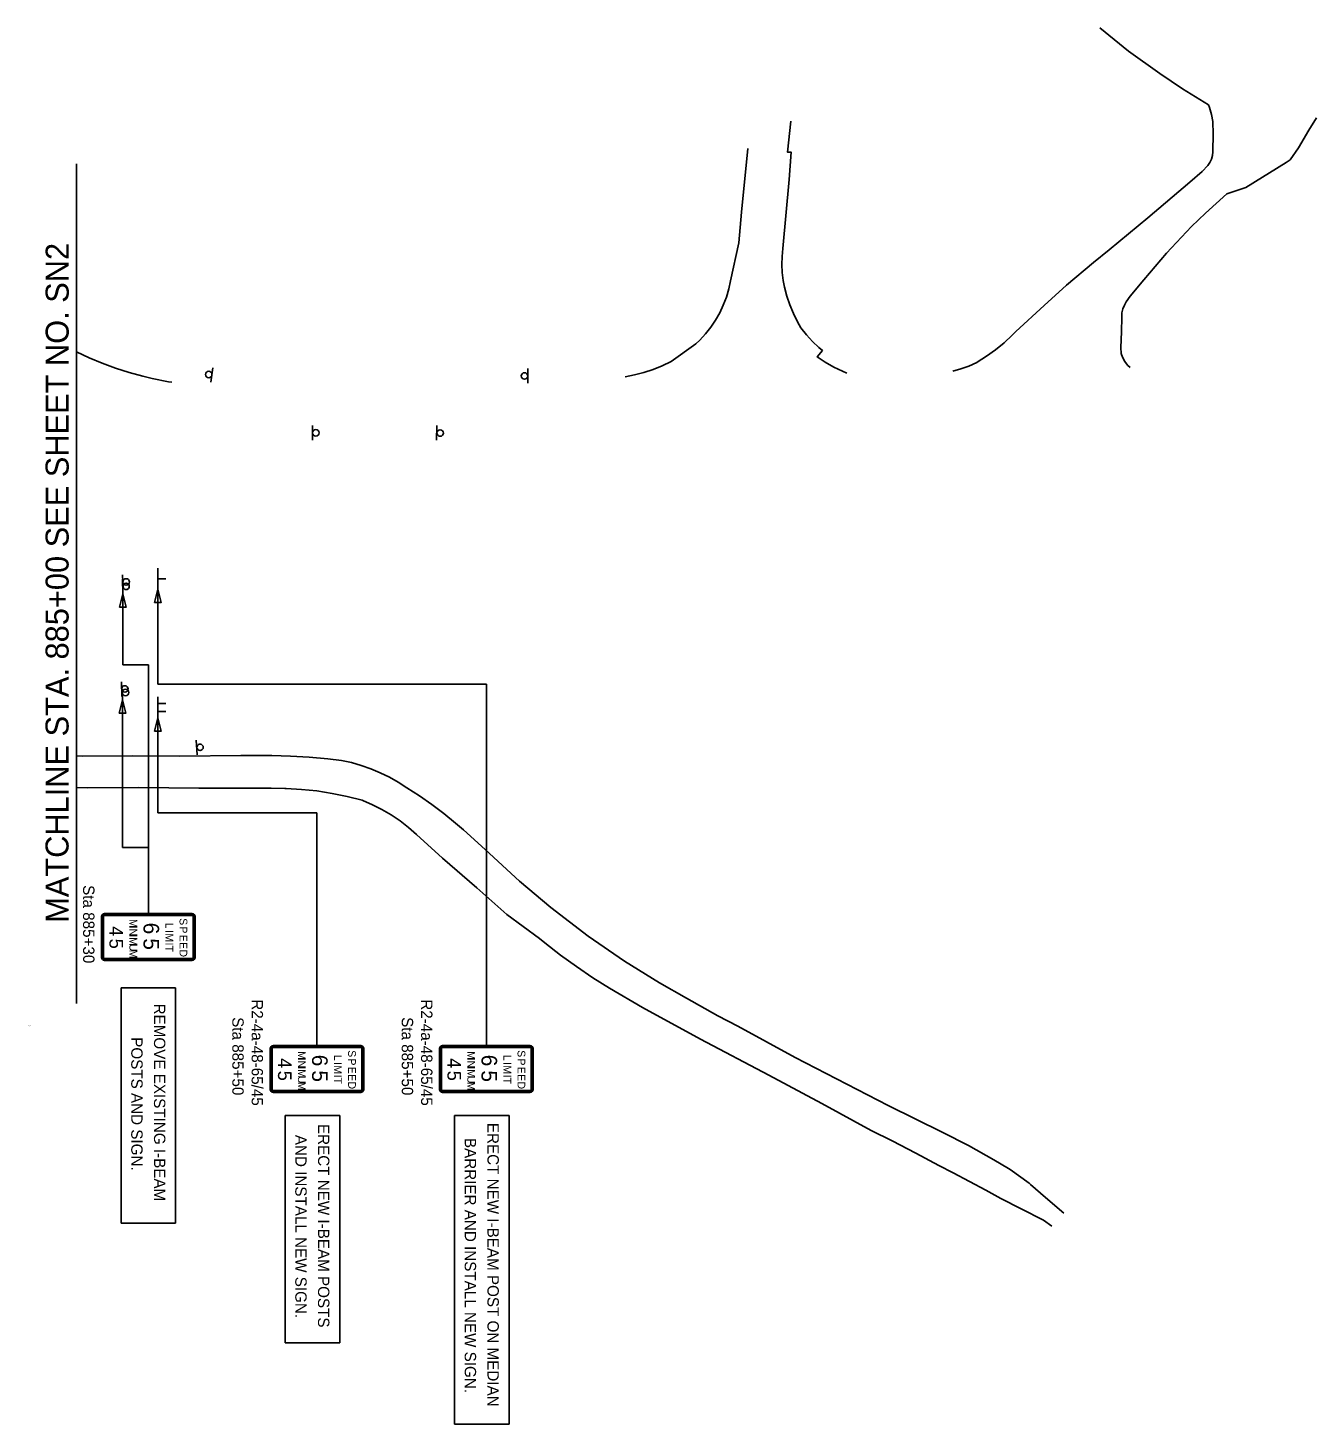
# Model space of a CAD drawing. Extents: x 1738774 to 1740360, y 1165523 to 1166492.
# Drawn here: x 1738774 to 1739567, y 1165523 to 1166383 of the extents above; entities that cross this region are included whole.
import ezdxf

# ---------------------------------------------------------------- set-up
doc = ezdxf.new("R2010")
doc.units = 0
for name, color, linetype in [('Default', 7, 'Continuous'), ('RD_EX_Road', 7, 'Continuous'), ('RD_SHT_MatchLine', 7, 'Continuous'), ('RD_SHT_TX', 7, 'Continuous'), ('SN_P_Signs', 7, 'Continuous')]:
    doc.layers.add(name, color=color, linetype=linetype)

msp = doc.modelspace()

# ---------------------------------------------------------------- linework, layer by layer
at = {"layer": 'RD_EX_Road'}
for points in [[(1739343.56, 1166171.83), (1739348.43, 1166173.2), (1739353.41, 1166175), (1739358.24, 1166177.18), (1739358.48, 1166177.3), (1739364.22, 1166180.98), (1739369.74, 1166184.98), (1739375.01, 1166189.3), (1739380.03, 1166193.91), (1739382.33, 1166196.21), (1739399.67, 1166212.18), (1739413.57, 1166224.69), (1739430.1, 1166238.68), (1739439.71, 1166246.44), (1739463.52, 1166266.19), (1739489.38, 1166288.25), (1739497.13, 1166294.74), (1739500.52, 1166298.46), (1739501.82, 1166300.32), (1739502.78, 1166302.38), (1739503.38, 1166304.57), (1739503.58, 1166306.84), (1739503.57, 1166307.3), (1739503.93, 1166317.85), (1739503.66, 1166325.46), (1739502.8, 1166329.83), (1739501.55, 1166334.1), (1739500.95, 1166335.76), (1739484.91, 1166345.58), (1739470.92, 1166355.04), (1739451.7, 1166368.78), (1739433.95, 1166383.18)], [(1739243.77, 1166325.81), (1739241.61, 1166306.77), (1739243.94, 1166306.58), (1739242.62, 1166289.86), (1739238.8, 1166247.42), (1739238.26, 1166242.48), (1739238.11, 1166237.51), (1739238.36, 1166232.55), (1739239, 1166227.62), (1739239.83, 1166223.56), (1739241.27, 1166218.02), (1739243.09, 1166212.6), (1739245.27, 1166207.31), (1739247.82, 1166202.19), (1739249.94, 1166198.49), (1739253.29, 1166194.2), (1739256.94, 1166190.16), (1739260.87, 1166186.4), (1739263.14, 1166184.46), (1739259.97, 1166180.57), (1739264.93, 1166177.3), (1739270.09, 1166174.36), (1739275.44, 1166171.77), (1739278.26, 1166170.63)], [(1739567.51, 1166327.79), (1739562.69, 1166320.3), (1739556.33, 1166309.34), (1739551.25, 1166302.04), (1739548.74, 1166300.37), (1739524.01, 1166284.98), (1739512.22, 1166281.11), (1739499.03, 1166269.04), (1739490.5, 1166260.93), (1739475.09, 1166244.45), (1739461.07, 1166227.99), (1739452.7, 1166217.92), (1739450.25, 1166214.49), (1739449.15, 1166212.56), (1739448.22, 1166210.17), (1739447.66, 1166207.67), (1739447.49, 1166205.12), (1739447.45, 1166196.13), (1739447.02, 1166186.49), (1739447.16, 1166182.73), (1739448.03, 1166180.45), (1739449.41, 1166177.86), (1739451.13, 1166175.48), (1739452.71, 1166174.02)], [(1739217.17, 1166308.92), (1739213.22, 1166269.83), (1739211.69, 1166250.8), (1739206.59, 1166227.55), (1739205.47, 1166222.44), (1739203.97, 1166217.43), (1739202.1, 1166212.55), (1739199.86, 1166207.83), (1739197.28, 1166203.29), (1739194.36, 1166198.95), (1739191.12, 1166194.85), (1739187.58, 1166191), (1739185.21, 1166188.73), (1739169.92, 1166177.74), (1739164.49, 1166175.13), (1739158.91, 1166172.88), (1739153.2, 1166171), (1739147.37, 1166169.5), (1739141.56, 1166168.41)], [(1738862.33, 1166165.02), (1738860.41, 1166165.33), (1738850.21, 1166167.38), (1738844.5, 1166168.7), (1738836.05, 1166170.99), (1738827.72, 1166173.66), (1738819.51, 1166176.71), (1738811.45, 1166180.12), (1738803.73, 1166183.8)], [(1738803.73, 1165934.87), (1738807.57, 1165934.84), (1738838.18, 1165934.92), (1738867.23, 1165934.84), (1738904.83, 1165935.06), (1738923.98, 1165935.14), (1738935.5, 1165934.85), (1738947.01, 1165934.17), (1738958.48, 1165933.09), (1738966.84, 1165932.06), (1738972.99, 1165930.76), (1738979.04, 1165929.07), (1738984.98, 1165927.01), (1738990.78, 1165924.58), (1738996.41, 1165921.78), (1739001.86, 1165918.65), (1739007.06, 1165915.2), (1739014.94, 1165910.27), (1739022.6, 1165905.01), (1739030.04, 1165899.43), (1739037.22, 1165893.54), (1739041.96, 1165889.37), (1739055.31, 1165877.27), (1739076.59, 1165857.76), (1739095.93, 1165841.52), (1739118.82, 1165823.93), (1739141.13, 1165808.47), (1739162.69, 1165795.26), (1739179.48, 1165785.83), (1739198.66, 1165774.79), (1739211, 1165768.54), (1739246.43, 1165749.26), (1739303.66, 1165719.64), (1739337.22, 1165702.99), (1739353.19, 1165694.92), (1739368.83, 1165686.17), (1739377.83, 1165680.77), (1739378.7, 1165680.25), (1739390.47, 1165671.75), (1739391.32, 1165671), (1739400.52, 1165662.94), (1739411.96, 1165653.33)], [(1738803.73, 1165915.38), (1738810.52, 1165915.34), (1738842.13, 1165915.46), (1738879.01, 1165915.07), (1738907.68, 1165915.04), (1738923.61, 1165914.97), (1738932.03, 1165914.83), (1738932.91, 1165914.75), (1738942.34, 1165914.23), (1738951.74, 1165913.31), (1738961.09, 1165911.81), (1738970.37, 1165909.92), (1738979.57, 1165907.65), (1738979.95, 1165907.5), (1738985.97, 1165904.87), (1738991.83, 1165901.88), (1738997.49, 1165898.55), (1739002.94, 1165894.89), (1739008.17, 1165890.9), (1739013.14, 1165886.61), (1739029.14, 1165871.95), (1739050.29, 1165853.65), (1739068.74, 1165837.19), (1739088.89, 1165822.5), (1739092.25, 1165819.77), (1739101.83, 1165812.31), (1739111.64, 1165805.17), (1739121.68, 1165798.35), (1739131.94, 1165791.86), (1739152.32, 1165779.92), (1739188.09, 1165760.47), (1739230.24, 1165738.34), (1739262.78, 1165720.95), (1739293.27, 1165704.27), (1739306.16, 1165697.89), (1739320.76, 1165690.38), (1739334.77, 1165682.75), (1739343.64, 1165678.09), (1739353.77, 1165672.79), (1739363.83, 1165667.51), (1739373.07, 1165662.47), (1739385.59, 1165655.93), (1739399.34, 1165649.13), (1739404.54, 1165645.36)]]:
    msp.add_lwpolyline(points, dxfattribs=at)
at = {"layer": 'RD_SHT_MatchLine'}
msp.add_lwpolyline([(1738803.73, 1165782.42), (1738803.73, 1166044.04), (1738803.73, 1166299.49)], dxfattribs=at)
at = {"layer": 'SN_P_Signs'}
for p, q in [((1738886.5, 1166164.99), (1738887.68, 1166173.91)), ((1739081.75, 1166164.38), (1739081.61, 1166173.38)), ((1738948.98, 1166138.34), (1738949.11, 1166129.34)), ((1739025.73, 1166138.3), (1739025.5, 1166129.3)), ((1738853.73, 1166037.52), (1738853.73, 1166050.56)), ((1738832.03, 1166043.77), (1738832.29, 1166034.77)), ((1738832.09, 1166046.49), (1738832.35, 1166037.5)), ((1738853.73, 1165979), (1738853.73, 1166044.04)), ((1738853.73, 1166044.04), (1738858.72, 1166044.04)), ((1738832.29, 1165991.08), (1738832.29, 1166034.77)), ((1738832.29, 1165991.08), (1738847.94, 1165991.08)), ((1738847.94, 1165837.82), (1738847.94, 1165991.08)), ((1738831.34, 1165980.59), (1738831.6, 1165971.59)), ((1738831.66, 1165978.39), (1738831.92, 1165969.4)), ((1738853.73, 1165979), (1739056.14, 1165979)), ((1739056.14, 1165756.51), (1739056.14, 1165979)), ((1738853.73, 1165958.27), (1738853.73, 1165971.31)), ((1738831.92, 1165878.58), (1738831.92, 1165969.4)), ((1738853.73, 1165967.2), (1738858.72, 1165967.2)), ((1738853.73, 1165962.18), (1738858.72, 1165962.18)), ((1738853.73, 1165899.82), (1738853.73, 1165958.27)), ((1738877.46, 1165944.58), (1738878.01, 1165935.6)), ((1738853.73, 1165899.82), (1738951.77, 1165899.82)), ((1738951.77, 1165756.51), (1738951.77, 1165899.82)), ((1738831.92, 1165878.58), (1738847.94, 1165878.58)), ((1738819.14, 1165810.82), (1738819.14, 1165836.02)), ((1738820.94, 1165837.82), (1738874.94, 1165837.82)), ((1738876.74, 1165836.02), (1738876.74, 1165810.82)), ((1738874.94, 1165809.02), (1738820.94, 1165809.02)), ((1738831.13, 1165647.11), (1738831.13, 1165792.13)), ((1738831.13, 1165792.13), (1738864.75, 1165792.13)), ((1738864.75, 1165792.13), (1738864.75, 1165647.11)), ((1738922.97, 1165729.51), (1738922.97, 1165754.71)), ((1738924.77, 1165756.51), (1738978.77, 1165756.51)), ((1738980.57, 1165754.71), (1738980.57, 1165729.51)), ((1739027.34, 1165729.51), (1739027.34, 1165754.71)), ((1739029.14, 1165756.51), (1739083.14, 1165756.51)), ((1739084.94, 1165754.71), (1739084.94, 1165729.51)), ((1738978.77, 1165727.71), (1738924.77, 1165727.71)), ((1739083.14, 1165727.71), (1739029.14, 1165727.71)), ((1738932.17, 1165573.46), (1738932.17, 1165713.48)), ((1738932.17, 1165713.48), (1738965.79, 1165713.48)), ((1738965.79, 1165713.48), (1738965.79, 1165573.46)), ((1739036.54, 1165523.46), (1739036.54, 1165713.48)), ((1739036.54, 1165713.48), (1739070.16, 1165713.48)), ((1739070.16, 1165713.48), (1739070.16, 1165523.46)), ((1738864.75, 1165647.11), (1738831.13, 1165647.11)), ((1738965.79, 1165573.46), (1738932.17, 1165573.46)), ((1739070.16, 1165523.46), (1739036.54, 1165523.46))]:
    msp.add_line(p, q, dxfattribs=at)
for points in [[(1738830.24, 1166026.57), (1738832.29, 1166034.77), (1738834.34, 1166026.57)], [(1738851.68, 1166029.32), (1738853.73, 1166037.52), (1738855.79, 1166029.32)], [(1738829.86, 1165961.19), (1738831.92, 1165969.4), (1738833.97, 1165961.19)], [(1738851.68, 1165950.07), (1738853.73, 1165958.27), (1738855.79, 1165950.07)]]:
    msp.add_lwpolyline(points, close=True, dxfattribs=at)
for points in [[(1738819.59, 1165810.82), (1738819.59, 1165836.02)], [(1738820.34, 1165810.82), (1738820.34, 1165836.02)], [(1738820.94, 1165837.37), (1738874.94, 1165837.37)], [(1738820.94, 1165836.62), (1738874.94, 1165836.62)], [(1738875.54, 1165836.02), (1738875.54, 1165810.82)], [(1738876.29, 1165836.02), (1738876.29, 1165810.82)], [(1738874.94, 1165810.22), (1738820.94, 1165810.22)], [(1738874.94, 1165809.47), (1738820.94, 1165809.47)], [(1738923.42, 1165729.51), (1738923.42, 1165754.71)], [(1738924.17, 1165729.51), (1738924.17, 1165754.71)], [(1738924.77, 1165756.06), (1738978.77, 1165756.06)], [(1738924.77, 1165755.31), (1738978.77, 1165755.31)], [(1738979.37, 1165754.71), (1738979.37, 1165729.51)], [(1738980.12, 1165754.71), (1738980.12, 1165729.51)], [(1739027.79, 1165729.51), (1739027.79, 1165754.71)], [(1739028.54, 1165729.51), (1739028.54, 1165754.71)], [(1739029.14, 1165756.06), (1739083.14, 1165756.06)], [(1739029.14, 1165755.31), (1739083.14, 1165755.31)], [(1739083.74, 1165754.71), (1739083.74, 1165729.51)], [(1739084.49, 1165754.71), (1739084.49, 1165729.51)], [(1738978.77, 1165728.91), (1738924.77, 1165728.91)], [(1738978.77, 1165728.16), (1738924.77, 1165728.16)], [(1739083.14, 1165728.91), (1739029.14, 1165728.91)], [(1739083.14, 1165728.16), (1739029.14, 1165728.16)]]:
    msp.add_lwpolyline(points, dxfattribs=at)
for centre in [(1738885.09, 1166169.73), (1739079.65, 1166168.86), (1738951.07, 1166133.85), (1739027.64, 1166133.73), (1738834.19, 1166039.31), (1738834.24, 1166042.03), (1738833.49, 1165976.13), (1738833.81, 1165973.93), (1738879.76, 1165940.2)]:
    msp.add_circle(centre, 2, dxfattribs=at)
for centre, radius, start, end in [((1738820.94, 1165836.02), 1.8, 90, 180), ((1738820.94, 1165836.02), 1.35, 90, 180), ((1738820.94, 1165836.02), 0.6, 90, 180), ((1738874.94, 1165836.02), 1.8, 0, 90), ((1738874.94, 1165836.02), 1.35, 0, 90), ((1738874.94, 1165836.02), 0.6, 0, 90), ((1738820.94, 1165810.82), 1.8, 180, 270), ((1738820.94, 1165810.82), 1.35, 180, 270), ((1738820.94, 1165810.82), 0.6, 180, 270), ((1738874.94, 1165810.82), 0.6, 270, 0), ((1738874.94, 1165810.82), 1.35, 270, 0), ((1738874.94, 1165810.82), 1.8, 270, 0), ((1738924.77, 1165754.71), 1.8, 90, 180), ((1738924.77, 1165754.71), 1.35, 90, 180), ((1738924.77, 1165754.71), 0.6, 90, 180), ((1738978.77, 1165754.71), 1.8, 0, 90), ((1738978.77, 1165754.71), 1.35, 0, 90), ((1738978.77, 1165754.71), 0.6, 0, 90), ((1739029.14, 1165754.71), 1.8, 90, 180), ((1739029.14, 1165754.71), 1.35, 90, 180), ((1739029.14, 1165754.71), 0.6, 90, 180), ((1739083.14, 1165754.71), 1.8, 0, 90), ((1739083.14, 1165754.71), 1.35, 0, 90), ((1739083.14, 1165754.71), 0.6, 0, 90), ((1738924.77, 1165729.51), 1.8, 180, 270), ((1738924.77, 1165729.51), 1.35, 180, 270), ((1738924.77, 1165729.51), 0.6, 180, 270), ((1738978.77, 1165729.51), 0.6, 270, 0), ((1738978.77, 1165729.51), 1.35, 270, 0), ((1738978.77, 1165729.51), 1.8, 270, 0), ((1739029.14, 1165729.51), 1.8, 180, 270), ((1739029.14, 1165729.51), 1.35, 180, 270), ((1739029.14, 1165729.51), 0.6, 180, 270), ((1739083.14, 1165729.51), 0.6, 270, 0), ((1739083.14, 1165729.51), 1.35, 270, 0), ((1739083.14, 1165729.51), 1.8, 270, 0)]:
    msp.add_arc(centre, radius, start, end, dxfattribs=at)

# ---------------------------------------------------------------- texts
at = {"layer": 'Default'}
for s, height, p in [('Angle:  16.0848', 0.2083, (1738773.73, 1165768.56)), ('Align: A_I85', 0.2083, (1738773.73, 1165768.29)), ('Sheet: 3', 0.208, (1738773.73, 1165768.83))]:
    msp.add_text(s, height=height, dxfattribs=at).set_placement(p)
at = {"layer": 'RD_SHT_TX'}
msp.add_text('MATCHLINE STA. 885+00 SEE SHEET NO. SN2', height=14.1726, rotation=89.98556, dxfattribs=at).set_placement((1738798.75, 1165832.14))
at = {"layer": 'SN_P_Signs'}
for s, height, rotation, p in [('Sta 885+30', 7, 270.00008, (1738807.72, 1165855.33)), ('M', 4.8, 270, (1738836.24, 1165834.42)), ('S', 4.8, 270, (1738867.14, 1165834.97)), ('4', 8.4, 270, (1738823.94, 1165830.11)), ('I', 4.8, 270, (1738836.24, 1165830.3)), ('N', 4.8, 270, (1738836.24, 1165828.61)), ('I', 4.8, 270, (1738836.24, 1165824.97)), ('6', 9.6, 270, (1738844.94, 1165832.21)), ('L', 4.8, 270, (1738858.44, 1165832.21)), ('I', 4.8, 270, (1738858.44, 1165827.69)), ('M', 4.8, 270, (1738858.44, 1165825.63)), ('P', 4.8, 270, (1738867.14, 1165829.87)), ('E', 4.8, 270, (1738867.14, 1165824.78)), ('5', 8.4, 270, (1738823.94, 1165822.37)), ('U', 4.8, 270, (1738836.24, 1165819.17)), ('M', 4.8, 270, (1738836.24, 1165823.29)), ('M', 4.8, 270, (1738836.24, 1165815.53)), ('5', 9.6, 270, (1738844.94, 1165822.58)), ('I', 4.8, 270, (1738858.44, 1165819.97)), ('T', 4.8, 270, (1738858.44, 1165818.15)), ('E', 4.8, 270, (1738867.14, 1165820.23)), ('D', 4.8, 270, (1738867.14, 1165815.69)), ('REMOVE EXISTING I-BEAM', 6.9998, 270.00008, (1738851.39, 1165782.38)), ('R2-4a-48-65/45', 7, 270.00008, (1738911.55, 1165785.04)), ('R2-4a-48-65/45', 7, 270.00008, (1739015.92, 1165785.04)), ('Sta 885+50', 7, 270.00008, (1738899.65, 1165774.02)), ('Sta 885+50', 7, 270.00008, (1739004.02, 1165774.02)), ('POSTS AND SIGN. ', 6.9998, 270.00008, (1738837.39, 1165761.68)), ('4', 8.4, 270, (1738927.77, 1165748.8)), ('M', 4.8, 270, (1738940.07, 1165753.11)), ('I', 4.8, 270, (1738940.07, 1165748.98)), ('N', 4.8, 270, (1738940.07, 1165747.3)), ('6', 9.6, 270, (1738948.77, 1165750.9)), ('L', 4.8, 270, (1738962.27, 1165750.9)), ('S', 4.8, 270, (1738970.97, 1165753.66)), ('P', 4.8, 270, (1738970.97, 1165748.56)), ('4', 8.4, 270, (1739032.14, 1165748.8)), ('M', 4.8, 270, (1739044.44, 1165753.11)), ('I', 4.8, 270, (1739044.44, 1165748.98)), ('N', 4.8, 270, (1739044.44, 1165747.3)), ('6', 9.6, 270, (1739053.14, 1165750.9)), ('L', 4.8, 270, (1739066.64, 1165750.9)), ('S', 4.8, 270, (1739075.34, 1165753.66)), ('P', 4.8, 270, (1739075.34, 1165748.56)), ('5', 8.4, 270, (1738927.77, 1165741.06)), ('I', 4.8, 270, (1738940.07, 1165743.66)), ('M', 4.8, 270, (1738940.07, 1165741.98)), ('5', 9.6, 270, (1738948.77, 1165741.27)), ('I', 4.8, 270, (1738962.27, 1165746.38)), ('M', 4.8, 270, (1738962.27, 1165744.32)), ('I', 4.8, 270, (1738962.27, 1165738.66)), ('E', 4.8, 270, (1738970.97, 1165743.46)), ('E', 4.8, 270, (1738970.97, 1165738.92)), ('5', 8.4, 270, (1739032.14, 1165741.06)), ('I', 4.8, 270, (1739044.44, 1165743.66)), ('M', 4.8, 270, (1739044.44, 1165741.98)), ('5', 9.6, 270, (1739053.14, 1165741.27)), ('I', 4.8, 270, (1739066.64, 1165746.38)), ('M', 4.8, 270, (1739066.64, 1165744.32)), ('I', 4.8, 270, (1739066.64, 1165738.66)), ('E', 4.8, 270, (1739075.34, 1165743.46)), ('E', 4.8, 270, (1739075.34, 1165738.92)), ('U', 4.8, 270, (1738940.07, 1165737.85)), ('M', 4.8, 270, (1738940.07, 1165734.22)), ('T', 4.8, 270, (1738962.27, 1165736.84)), ('D', 4.8, 270, (1738970.97, 1165734.38)), ('U', 4.8, 270, (1739044.44, 1165737.85)), ('M', 4.8, 270, (1739044.44, 1165734.22)), ('T', 4.8, 270, (1739066.64, 1165736.84)), ('D', 4.8, 270, (1739075.34, 1165734.38)), ('ERECT NEW I-BEAM POSTS', 6.9998, 270.00008, (1738952.43, 1165708.25)), ('ERECT NEW I-BEAM POST ON MEDIAN ', 6.9998, 270.00008, (1739056.8, 1165708.92)), ('AND INSTALL NEW SIGN.', 6.9998, 270.00008, (1738938.43, 1165701.56)), ('BARRIER AND INSTALL NEW SIGN.', 6.9998, 270.00008, (1739042.8, 1165699.66))]:
    msp.add_text(s, height=height, rotation=rotation, dxfattribs=at).set_placement(p)

doc.saveas('drawing.dxf')
